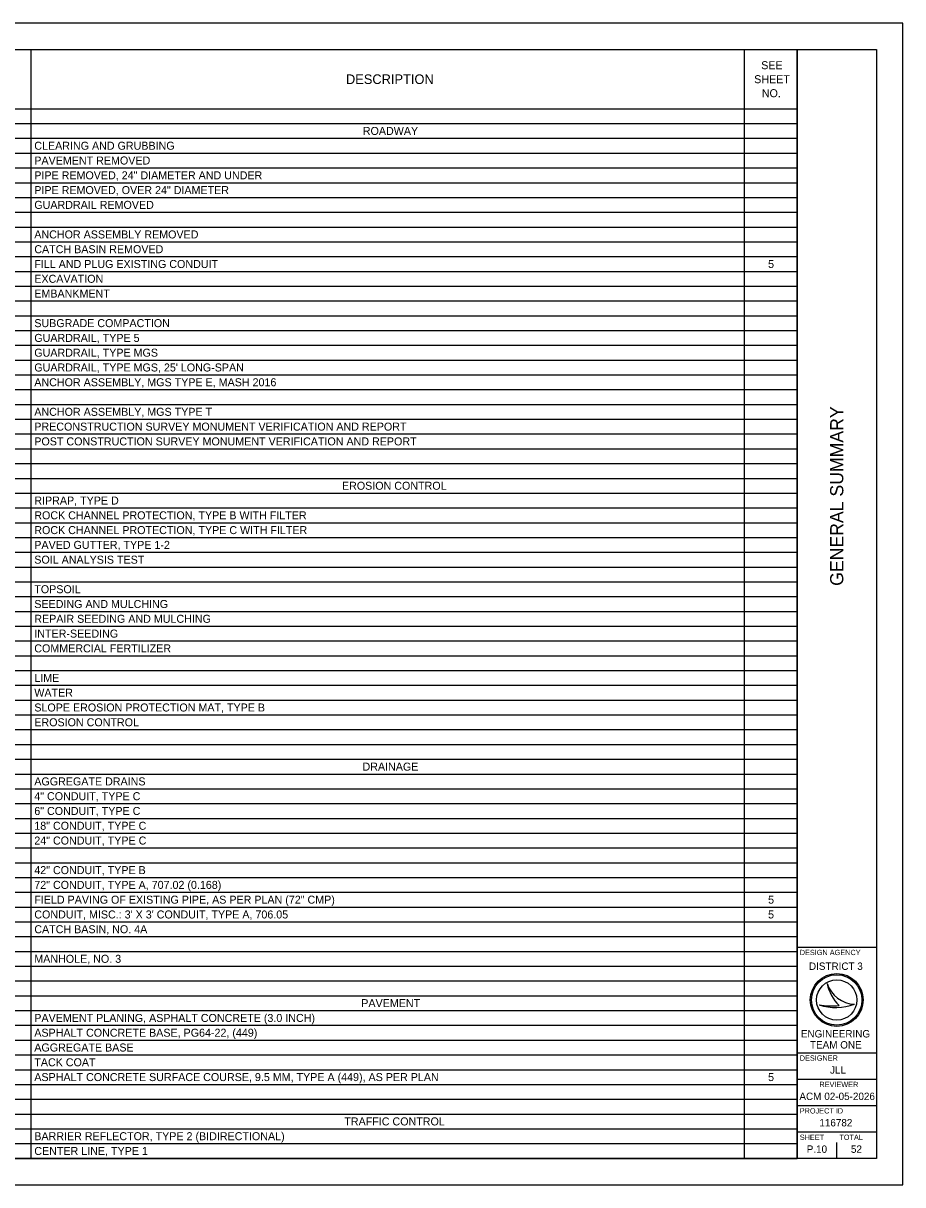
# Model space of a CAD drawing. Extents: x 0 to 34, y 0 to 22.
# Drawn here: x 17.35 to 34, y 0 to 22 of the extents above; entities that cross this region are included whole.
import ezdxf

# ---------------------------------------------------------------- set-up
doc = ezdxf.new("R2010")
doc.units = 0
for name, color, linetype in [('Default', 7, 'Continuous'), ('SH_Border', 7, 'Continuous'), ('SH_Cut_Line', 7, 'Continuous'), ('SH_Data', 7, 'Continuous')]:
    doc.layers.add(name, color=color, linetype=linetype)

msp = doc.modelspace()

# ---------------------------------------------------------------- linework, layer by layer
at = {"layer": 'Default'}
for p, q in [((1.5, 21.5), (32, 21.5)), ((17.491, 21.5), (17.491, 0.5)), ((30.995, 21.5), (30.995, 0.5)), ((32, 21.5), (32, 0.5)), ((1.5, 20.38), (32, 20.38)), ((1.5, 20.1), (32, 20.1)), ((1.5, 19.82), (32, 19.82)), ((1.5, 19.54), (32, 19.54)), ((1.5, 19.26), (32, 19.26)), ((1.5, 18.98), (32, 18.98)), ((1.5, 18.7), (32, 18.7)), ((1.5, 18.42), (32, 18.42)), ((1.5, 18.14), (32, 18.14)), ((1.5, 17.86), (32, 17.86)), ((1.5, 17.58), (32, 17.58)), ((1.5, 17.3), (32, 17.3)), ((1.5, 17.02), (32, 17.02)), ((1.5, 16.74), (32, 16.74)), ((1.5, 16.46), (32, 16.46)), ((1.5, 16.18), (32, 16.18)), ((1.5, 15.9), (32, 15.9)), ((1.5, 15.62), (32, 15.62)), ((1.5, 15.34), (32, 15.34)), ((1.5, 15.06), (32, 15.06)), ((1.5, 14.78), (32, 14.78)), ((1.5, 14.5), (32, 14.5)), ((1.5, 14.22), (32, 14.22)), ((1.5, 13.94), (32, 13.94)), ((1.5, 13.66), (32, 13.66)), ((1.5, 13.38), (32, 13.38)), ((1.5, 13.1), (32, 13.1)), ((1.5, 12.82), (32, 12.82)), ((1.5, 12.54), (32, 12.54)), ((1.5, 12.26), (32, 12.26)), ((1.5, 11.98), (32, 11.98)), ((1.5, 11.7), (32, 11.7)), ((1.5, 11.42), (32, 11.42)), ((1.5, 11.14), (32, 11.14)), ((1.5, 10.86), (32, 10.86)), ((1.5, 10.58), (32, 10.58)), ((1.5, 10.3), (32, 10.3)), ((1.5, 10.02), (32, 10.02)), ((1.5, 9.74), (32, 9.74)), ((1.5, 9.46), (32, 9.46)), ((1.5, 9.18), (32, 9.18)), ((1.5, 8.9), (32, 8.9)), ((1.5, 8.62), (32, 8.62)), ((1.5, 8.34), (32, 8.34)), ((1.5, 8.06), (32, 8.06)), ((1.5, 7.78), (32, 7.78)), ((1.5, 7.5), (32, 7.5)), ((1.5, 7.22), (32, 7.22)), ((1.5, 6.94), (32, 6.94)), ((1.5, 6.66), (32, 6.66)), ((1.5, 6.38), (32, 6.38)), ((1.5, 6.1), (32, 6.1)), ((1.5, 5.82), (32, 5.82)), ((1.5, 5.54), (32, 5.54)), ((1.5, 5.26), (32, 5.26)), ((1.5, 4.98), (32, 4.98)), ((1.5, 4.7), (32, 4.7)), ((1.5, 4.42), (32, 4.42)), ((1.5, 4.14), (32, 4.14)), ((1.5, 3.86), (32, 3.86)), ((1.5, 3.58), (32, 3.58)), ((1.5, 3.3), (32, 3.3)), ((1.5, 3.02), (32, 3.02)), ((1.5, 2.74), (32, 2.74)), ((1.5, 2.46), (32, 2.46)), ((1.5, 2.18), (32, 2.18)), ((1.5, 1.9), (32, 1.9)), ((1.5, 1.62), (32, 1.62)), ((1.5, 1.34), (32, 1.34)), ((1.5, 1.06), (32, 1.06)), ((1.5, 0.78), (32, 0.78)), ((1.5, 0.5), (32, 0.5))]:
    msp.add_line(p, q, dxfattribs=at)
at = {"layer": 'SH_Border'}
for p, q in [((32, 0.5), (32, 21.5)), ((32, 4.5), (33.5, 4.5)), ((32, 2.5), (33.5, 2.5)), ((32, 2), (33.5, 2)), ((32, 1.5), (33.5, 1.5)), ((32, 1), (33.5, 1))]:
    msp.add_line(p, q, dxfattribs=at)
msp.add_lwpolyline([(1.5, 21.5), (33.5, 21.5), (33.5, 0.5), (1.5, 0.5)], close=True, dxfattribs=at)
at = {"layer": 'SH_Cut_Line'}
msp.add_lwpolyline([(0, 0), (34, 0), (34, 22), (0, 22)], close=True, dxfattribs=at)
at = {"layer": 'SH_Data'}
for p, q in [((32.567, 3.81), (32.567, 3.81)), ((32.417, 3.41), (32.417, 3.41)), ((32.75, 3.5), (32.75, 3.5)), ((33.087, 3.419), (33.087, 3.419)), ((32.375, 0.675), (32.375, 0.675)), ((32.75, 0.5), (32.75, 0.8))]:
    msp.add_line(p, q, dxfattribs=at)
for radius in [0.5, 0.477, 0.477, 0.382]:
    msp.add_circle((32.75, 3.5), radius, dxfattribs=at)
for centre, radius, start, end in [((33.116, 3.998), 0.58, 198.9257, 198.9319), ((33.347, 3.97), 0.796, 191.6379, 191.6421), ((33.116, 3.998), 0.58, 198.9319, 267.1657), ((33.347, 3.97), 0.796, 191.6421, 226.0947), ((32.739, 4.37), 1.013, 251.4576, 290.0832), ((32.648, 4.654), 1.266, 259.4964, 259.4995), ((32.739, 4.37), 1.013, 251.4527, 251.4576), ((32.648, 4.654), 1.266, 259.4995, 276.6672)]:
    msp.add_arc(centre, radius, start, end, dxfattribs=at)

# ---------------------------------------------------------------- texts
at = {"layer": 'Default'}
for s, height, p in [('SEE ', 0.1515, (31.32, 21.129)), ('DESCRIPTION', 0.18184, (23.458, 20.849)), ('SHEET ', 0.1515, (31.187, 20.864)), ('NO.', 0.1515, (31.331, 20.599)), ('ROADWAY', 0.1515, (23.777, 19.884)), ('CLEARING AND GRUBBING', 0.15153, (17.557, 19.604)), ('PAVEMENT REMOVED', 0.15153, (17.557, 19.324)), ('PIPE REMOVED, 24" DIAMETER AND UNDER', 0.15153, (17.557, 19.044)), ('PIPE REMOVED, OVER 24" DIAMETER', 0.15153, (17.557, 18.764)), ('GUARDRAIL REMOVED', 0.15153, (17.557, 18.484)), ('ANCHOR ASSEMBLY REMOVED', 0.15153, (17.557, 17.924)), ('CATCH BASIN REMOVED', 0.15153, (17.557, 17.644)), ('FILL AND PLUG EXISTING CONDUIT', 0.15153, (17.557, 17.364)), ('5', 0.152, (31.45, 17.364)), ('EXCAVATION', 0.1515, (17.557, 17.084)), ('EMBANKMENT', 0.1515, (17.557, 16.804)), ('SUBGRADE COMPACTION', 0.15153, (17.557, 16.244)), ('GUARDRAIL, TYPE 5', 0.15153, (17.557, 15.964)), ('GUARDRAIL, TYPE MGS', 0.15153, (17.557, 15.684)), ("GUARDRAIL, TYPE MGS, 25' LONG-SPAN", 0.15153, (17.557, 15.404)), ('ANCHOR ASSEMBLY, MGS TYPE E, MASH 2016', 0.15153, (17.557, 15.124)), ('ANCHOR ASSEMBLY, MGS TYPE T', 0.15153, (17.557, 14.564)), ('PRECONSTRUCTION SURVEY MONUMENT VERIFICATION AND REPORT', 0.15153, (17.557, 14.284)), ('POST CONSTRUCTION SURVEY MONUMENT VERIFICATION AND REPORT', 0.15153, (17.557, 14.004)), ('EROSION CONTROL', 0.15153, (23.382, 13.164)), ('RIPRAP, TYPE D', 0.15153, (17.557, 12.884)), ('ROCK CHANNEL PROTECTION, TYPE B WITH FILTER', 0.15153, (17.557, 12.604)), ('ROCK CHANNEL PROTECTION, TYPE C WITH FILTER', 0.15153, (17.557, 12.324)), ('PAVED GUTTER, TYPE 1-2', 0.15153, (17.557, 12.044)), ('SOIL ANALYSIS TEST', 0.15153, (17.557, 11.764)), ('TOPSOIL', 0.1515, (17.557, 11.204)), ('SEEDING AND MULCHING', 0.15153, (17.557, 10.924)), ('REPAIR SEEDING AND MULCHING', 0.15153, (17.557, 10.644)), ('INTER-SEEDING', 0.15153, (17.557, 10.364)), ('COMMERCIAL FERTILIZER', 0.15153, (17.557, 10.084)), ('LIME', 0.1515, (17.557, 9.524)), ('WATER', 0.1515, (17.557, 9.244)), ('SLOPE EROSION PROTECTION MAT, TYPE B', 0.15153, (17.557, 8.964)), ('EROSION CONTROL', 0.15153, (17.557, 8.684)), ('DRAINAGE', 0.1515, (23.771, 7.844)), ('AGGREGATE DRAINS', 0.15153, (17.557, 7.564)), ('4" CONDUIT, TYPE C', 0.15153, (17.557, 7.284)), ('6" CONDUIT, TYPE C', 0.15153, (17.557, 7.004)), ('18" CONDUIT, TYPE C', 0.15153, (17.557, 6.724)), ('24" CONDUIT, TYPE C', 0.15153, (17.557, 6.444)), ('42" CONDUIT, TYPE B', 0.15153, (17.557, 5.884)), ('72" CONDUIT, TYPE A, 707.02 (0.168)', 0.15153, (17.557, 5.604)), ('FIELD PAVING OF EXISTING PIPE, AS PER PLAN (72" CMP)', 0.15153, (17.557, 5.324)), ('5', 0.152, (31.45, 5.324)), ("CONDUIT, MISC.: 3' X 3' CONDUIT, TYPE A, 706.05", 0.15153, (17.557, 5.044)), ('5', 0.152, (31.45, 5.044)), ('CATCH BASIN, NO. 4A', 0.15153, (17.557, 4.764)), ('MANHOLE, NO. 3', 0.15153, (17.557, 4.204)), ('PAVEMENT', 0.1515, (23.748, 3.364)), ('PAVEMENT PLANING, ASPHALT CONCRETE (3.0 INCH)', 0.15153, (17.557, 3.084)), ('ASPHALT CONCRETE BASE, PG64-22, (449)', 0.15153, (17.557, 2.804)), ('AGGREGATE BASE', 0.15153, (17.557, 2.524)), ('TACK COAT', 0.1515, (17.557, 2.244)), ('ASPHALT CONCRETE SURFACE COURSE, 9.5 MM, TYPE A (449), AS PER PLAN', 0.15153, (17.557, 1.964)), ('5', 0.152, (31.45, 1.964)), ('TRAFFIC CONTROL', 0.15153, (23.427, 1.124)), ('BARRIER REFLECTOR, TYPE 2 (BIDIRECTIONAL)', 0.15153, (17.557, 0.844)), ('CENTER LINE, TYPE 1', 0.15153, (17.557, 0.564))]:
    msp.add_text(s, height=height, dxfattribs=at).set_placement(p)
at = {"layer": 'SH_Data'}
msp.add_text('GENERAL SUMMARY', height=0.25, rotation=90, dxfattribs=at).set_placement((32.875, 11.344))
for s, height, p in [('DESIGN AGENCY', 0.1, (32.05, 4.35)), ('DISTRICT 3', 0.14, (32.224, 4.07)), ('ENGINEERING', 0.14, (32.071, 2.79)), ('TEAM ONE', 0.14, (32.244, 2.58)), ('DESIGNER', 0.1, (32.05, 2.35)), ('JLL', 0.14, (32.623, 2.105)), ('REVIEWER', 0.1, (32.422, 1.85)), ('ACM', 0.14, (32.043, 1.605)), ('02-05-2026', 0.14, (32.515, 1.605)), ('PROJECT ID', 0.1, (32.05, 1.35)), ('116782', 0.14, (32.421, 1.105)), ('SHEET', 0.1, (32.05, 0.85)), ('TOTAL', 0.1, (32.8, 0.85)), ('P.10', 0.14, (32.182, 0.605)), ('52', 0.14, (33.019, 0.605))]:
    msp.add_text(s, height=height, dxfattribs=at).set_placement(p)

doc.saveas('drawing.dxf')
